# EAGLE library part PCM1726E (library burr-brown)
Stereo Audio DAC 16 bit, 96KHz sampling
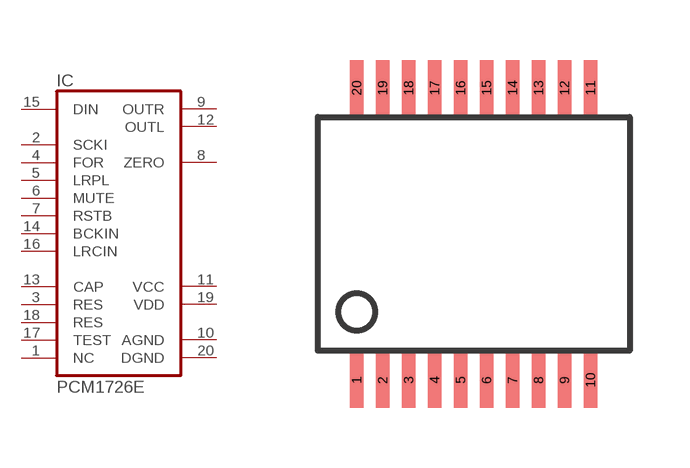
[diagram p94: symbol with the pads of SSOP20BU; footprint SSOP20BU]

Designator prefix IC

## PCM1726E (OC_FARNELL: unknown; OC_NEWARK: unknown)  [SSOP20BU]
1  NC  nc
2  SCKI  in
3  RES  pas
4  FOR  in
5  LRPL  in
6  MUTE  in
7  RSTB  in
8  ZERO  out
9  OUTR  out
10  AGND  pwr
11  VCC  pwr
12  OUTL  out
13  CAP  pas
14  BCKIN  in
15  DIN  in
16  LRCIN  in
17  TEST  pas
18  RES  pas
19  VDD  pwr
20  DGND  pwr

## Footprint SSOP20BU (pad centres in mm)
Small Shrink Outline Package
smd 0.348 x 1.397: 1 -2.925,-3.656; 2 -2.275,-3.656; 3 -1.625,-3.656; 4 -0.975,-3.656; 5 -0.325,-3.656; 6 0.325,-3.656; 7 0.975,-3.656; 8 1.625,-3.656; 9 2.275,-3.656; 10 2.925,-3.656; 11 2.925,3.656; 12 2.275,3.656; 13 1.625,3.656; 14 0.975,3.656; 15 0.325,3.656; 16 -0.325,3.656; 17 -0.975,3.656; 18 -1.625,3.656; 19 -2.275,3.656; 20 -2.925,3.656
